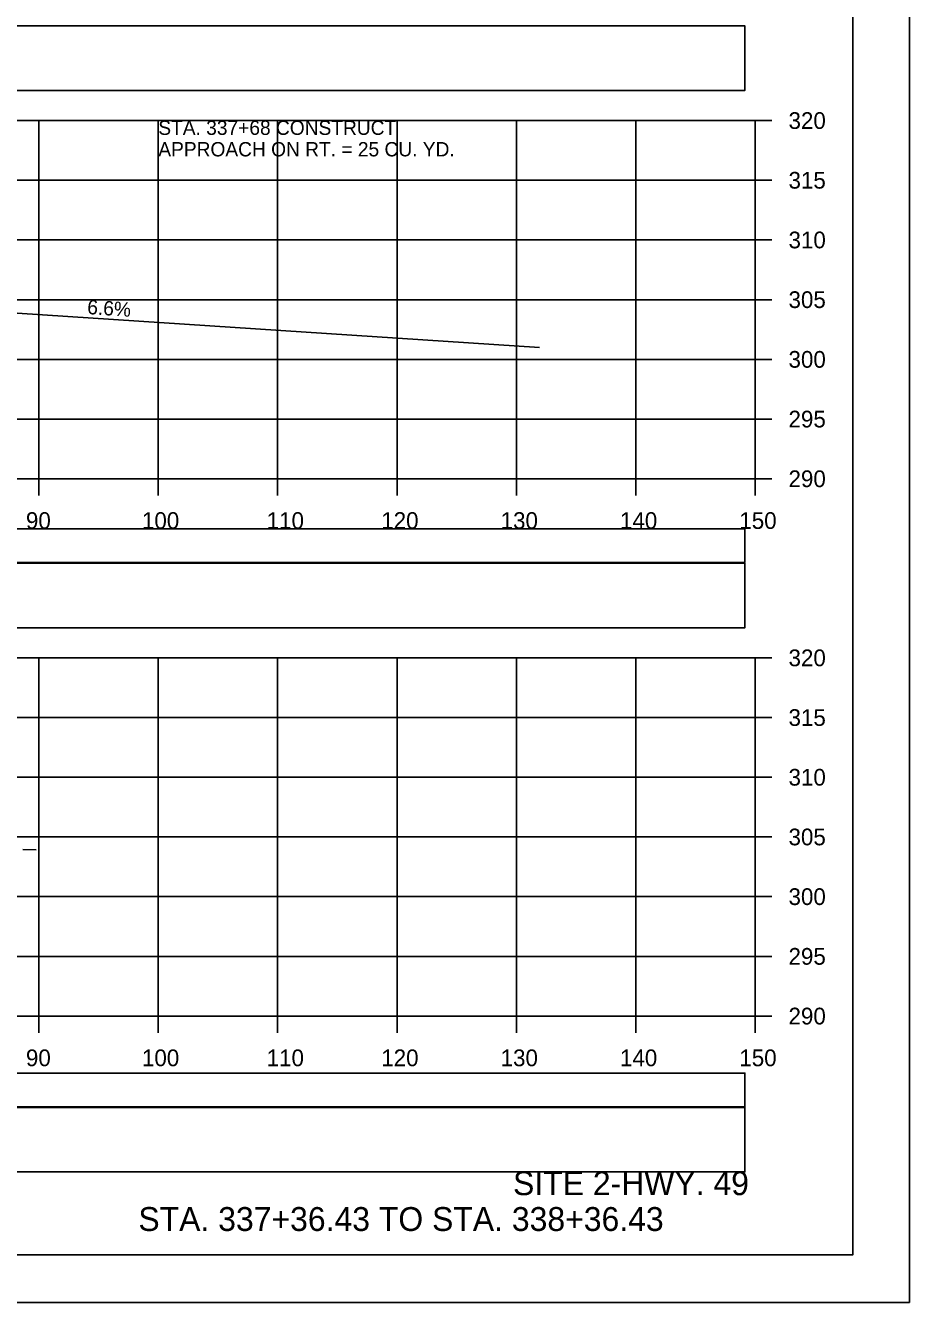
# Model space of a CAD drawing. Extents: x 1368122 to 1710785, y 373130 to 557566.
# Drawn here: x 1370777.8 to 1370851.9, y 373557 to 373663.9 of the extents above; entities that cross this region are included whole.
import ezdxf

# ---------------------------------------------------------------- set-up
doc = ezdxf.new("R2010")
doc.units = 0
for name, color, linetype in [('R_Axis', 7, 'Continuous'), ('R_Axis Annot', 7, 'Continuous'), ('R_Border', 7, 'Continuous'), ('R_Draft', 7, 'Continuous'), ('R_Drive', 7, 'Continuous'), ('R_Exist Surface', 7, 'Continuous'), ('R_Grid', 7, 'Continuous'), ('R_No Plot', 7, 'Continuous'), ('R_Water Annot', 7, 'Continuous'), ('R_Xsect Elev', 7, 'Continuous')]:
    doc.layers.add(name, color=color, linetype=linetype)

msp = doc.modelspace()

# ---------------------------------------------------------------- linework, layer by layer
for points in [[(1370539.77, 373658.51), (1370838.07, 373658.51), (1370838.07, 373663.92), (1370539.77, 373663.92)], [(1370539.77, 373618.98), (1370838.07, 373618.98), (1370838.07, 373621.79), (1370539.77, 373621.79)], [(1370539.77, 373613.51), (1370838.07, 373613.51), (1370838.07, 373618.92), (1370539.77, 373618.92)], [(1370539.77, 373573.4), (1370838.07, 373573.4), (1370838.07, 373576.21), (1370539.77, 373576.21)], [(1370539.77, 373567.93), (1370838.07, 373567.93), (1370838.07, 373573.34), (1370539.77, 373573.34)]]:
    msp.add_lwpolyline(points, close=True)
at = {"layer": 'R_Axis'}
for p, q in [((1370838.92, 373625.99), (1370838.92, 373655.99)), ((1370840.32, 373655.99), (1370838.92, 373655.99)), ((1370840.32, 373650.99), (1370838.92, 373650.99)), ((1370840.32, 373645.99), (1370838.92, 373645.99)), ((1370840.32, 373640.99), (1370838.92, 373640.99)), ((1370840.32, 373635.99), (1370838.92, 373635.99)), ((1370840.32, 373630.99), (1370838.92, 373630.99)), ((1370538.92, 373625.99), (1370838.92, 373625.99)), ((1370778.92, 373624.59), (1370778.92, 373625.99)), ((1370788.92, 373624.59), (1370788.92, 373625.99)), ((1370798.92, 373624.59), (1370798.92, 373625.99)), ((1370808.92, 373624.59), (1370808.92, 373625.99)), ((1370818.92, 373624.59), (1370818.92, 373625.99)), ((1370828.92, 373624.59), (1370828.92, 373625.99)), ((1370838.92, 373624.59), (1370838.92, 373625.99)), ((1370840.32, 373625.99), (1370838.92, 373625.99)), ((1370838.92, 373580.99), (1370838.92, 373610.99)), ((1370840.32, 373610.99), (1370838.92, 373610.99)), ((1370840.32, 373605.99), (1370838.92, 373605.99)), ((1370840.32, 373600.99), (1370838.92, 373600.99)), ((1370840.32, 373595.99), (1370838.92, 373595.99)), ((1370840.32, 373590.99), (1370838.92, 373590.99)), ((1370840.32, 373585.99), (1370838.92, 373585.99)), ((1370538.92, 373580.99), (1370838.92, 373580.99)), ((1370778.92, 373579.59), (1370778.92, 373580.99)), ((1370788.92, 373579.59), (1370788.92, 373580.99)), ((1370798.92, 373579.59), (1370798.92, 373580.99)), ((1370808.92, 373579.59), (1370808.92, 373580.99)), ((1370818.92, 373579.59), (1370818.92, 373580.99)), ((1370828.92, 373579.59), (1370828.92, 373580.99)), ((1370838.92, 373579.59), (1370838.92, 373580.99)), ((1370840.32, 373580.99), (1370838.92, 373580.99))]:
    msp.add_line(p, q, dxfattribs=at)
at = {"layer": 'R_Border'}
for q in [(1370847.1, 373766.45), (1370530.92, 373560.99)]:
    msp.add_line((1370847.1, 373560.99), q, dxfattribs=at)
at = {"layer": 'R_Exist Surface'}
msp.add_lwpolyline([(1370777.56, 373594.93), (1370778.68, 373594.91)], dxfattribs=at)
at = {"layer": 'R_Grid'}
for p, q in [((1370538.92, 373655.99), (1370838.92, 373655.99)), ((1370778.92, 373625.99), (1370778.92, 373655.99)), ((1370788.92, 373625.99), (1370788.92, 373655.99)), ((1370798.92, 373625.99), (1370798.92, 373655.99)), ((1370808.92, 373625.99), (1370808.92, 373655.99)), ((1370818.92, 373625.99), (1370818.92, 373655.99)), ((1370828.92, 373625.99), (1370828.92, 373655.99)), ((1370838.92, 373625.99), (1370838.92, 373655.99)), ((1370538.92, 373650.99), (1370838.92, 373650.99)), ((1370538.92, 373645.99), (1370838.92, 373645.99)), ((1370538.92, 373640.99), (1370838.92, 373640.99)), ((1370538.92, 373635.99), (1370838.92, 373635.99)), ((1370538.92, 373630.99), (1370838.92, 373630.99)), ((1370538.92, 373625.99), (1370838.92, 373625.99)), ((1370538.92, 373610.99), (1370838.92, 373610.99)), ((1370778.92, 373580.99), (1370778.92, 373610.99)), ((1370788.92, 373580.99), (1370788.92, 373610.99)), ((1370798.92, 373580.99), (1370798.92, 373610.99)), ((1370808.92, 373580.99), (1370808.92, 373610.99)), ((1370818.92, 373580.99), (1370818.92, 373610.99)), ((1370828.92, 373580.99), (1370828.92, 373610.99)), ((1370838.92, 373580.99), (1370838.92, 373610.99)), ((1370538.92, 373605.99), (1370838.92, 373605.99)), ((1370538.92, 373600.99), (1370838.92, 373600.99)), ((1370538.92, 373595.99), (1370838.92, 373595.99)), ((1370538.92, 373590.99), (1370838.92, 373590.99)), ((1370538.92, 373585.99), (1370838.92, 373585.99)), ((1370538.92, 373580.99), (1370838.92, 373580.99))]:
    msp.add_line(p, q, dxfattribs=at)
at = {"layer": 'R_No Plot'}
msp.add_line((1370518.52, 373557.01), (1370851.85, 373557.01), dxfattribs=at)
for points in [[(1370518.51, 373770.34), (1370851.85, 373770.34), (1370851.85, 373557), (1370518.51, 373557)], [(1370764.84, 373766.45), (1370784.46, 373766.45), (1370784.46, 373756.57), (1370800.57, 373756.57), (1370823.77, 373756.57), (1370823.89, 373728.41), (1370847.1, 373728.41), (1370847.1, 373560.99), (1370530.92, 373560.99), (1370530.92, 373766.45)]]:
    msp.add_lwpolyline(points, close=True, dxfattribs=at)
at = {"layer": 'R_Xsect Elev'}
msp.add_line((1370820.87, 373636.97), (1370756.62, 373641.21), dxfattribs=at)

# ---------------------------------------------------------------- texts
at = {"layer": 'R_Axis Annot'}
for s, p in [('320', (1370841.72, 373655.29)), ('315', (1370841.72, 373650.29)), ('310', (1370841.72, 373645.29)), ('305', (1370841.72, 373640.29)), ('300', (1370841.72, 373635.29)), ('295', (1370841.72, 373630.29)), ('290', (1370841.72, 373625.29)), ('90', (1370777.83, 373621.79)), ('100', (1370787.55, 373621.79)), ('110', (1370798, 373621.79)), ('120', (1370807.6, 373621.79)), ('130', (1370817.6, 373621.79)), ('140', (1370827.6, 373621.79)), ('150', (1370837.6, 373621.79)), ('320', (1370841.72, 373610.29)), ('315', (1370841.72, 373605.29)), ('310', (1370841.72, 373600.29)), ('305', (1370841.72, 373595.29)), ('300', (1370841.72, 373590.29)), ('295', (1370841.72, 373585.29)), ('290', (1370841.72, 373580.29)), ('90', (1370777.83, 373576.79)), ('100', (1370787.55, 373576.79)), ('110', (1370798, 373576.79)), ('120', (1370807.6, 373576.79)), ('130', (1370817.6, 373576.79)), ('140', (1370827.6, 373576.79)), ('150', (1370837.6, 373576.79))]:
    msp.add_text(s, height=1.4, dxfattribs=at).set_placement(p)
at = {"layer": 'R_Draft'}
for s, p in [('SITE 2-HWY. 49', (1370818.64, 373565.99)), ('STA. 337+36.43 TO STA. 338+36.43', (1370787.25, 373562.99))]:
    msp.add_text(s, height=2, dxfattribs=at).set_placement(p)
at = {"layer": 'R_Drive'}
msp.add_text('6.6%', height=1.2, rotation=356.2242, dxfattribs=at).set_placement((1370782.94, 373639.79))
at = {"layer": 'R_Water Annot'}
for s, p in [('STA. 337+68 CONSTRUCT', (1370788.92, 373654.79)), ('APPROACH ON RT. = 25 CU. YD.', (1370788.92, 373652.99))]:
    msp.add_text(s, height=1.2, dxfattribs=at).set_placement(p)

doc.saveas('drawing.dxf')
